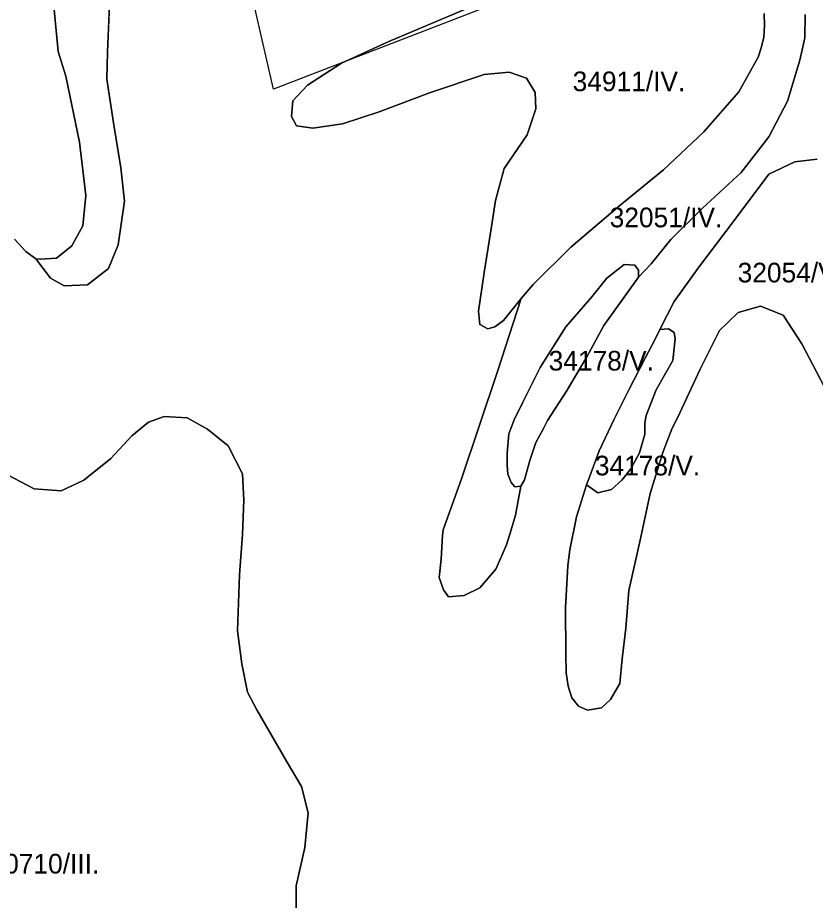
# Model space of a CAD drawing. Extents: x -521621 to -516761, y -1190184 to -1184927.
# Drawn here: x -520715 to -520107, y -1188092 to -1187419 of the extents above; entities that cross this region are included whole.
import ezdxf

# ---------------------------------------------------------------- set-up
doc = ezdxf.new("R2010")
doc.units = 0
doc.layers.add('BPEJ_s', color=7, linetype='Continuous')
doc.layers.add('odvodneni_s', color=7, linetype='Continuous')

msp = doc.modelspace()

# ---------------------------------------------------------------- linework, layer by layer
at = {"layer": 'BPEJ_s'}
for p, q in [((-520646.81, -1187445.43), (-520644.86, -1187402.32)), ((-520358.86, -1187406.5), (-520432.14, -1187437.52)), ((-520115.05, -1187434.6), (-520114.84, -1187416.89)), ((-520432.14, -1187437.52), (-520468.22, -1187453.88)), ((-520117.15, -1187443.67), (-520115.05, -1187434.6)), ((-520647.21, -1187466.2), (-520646.81, -1187445.43)), ((-520118.83, -1187451.64), (-520117.15, -1187443.67)), ((-520468.22, -1187453.88), (-520494.15, -1187470.8)), ((-520128.33, -1187482.99), (-520118.83, -1187451.64)), ((-520642.11, -1187499.52), (-520647.21, -1187466.2)), ((-520401.13, -1187476.44), (-520359.55, -1187462.56)), ((-520359.55, -1187462.56), (-520340.56, -1187460.66)), ((-520340.56, -1187460.66), (-520327.27, -1187465.42)), ((-520327.27, -1187465.42), (-520320.62, -1187476.34)), ((-520494.15, -1187470.8), (-520505.42, -1187482.65)), ((-520439.47, -1187491.11), (-520401.13, -1187476.44)), ((-520320.62, -1187476.34), (-520320.15, -1187488.69)), ((-520505.42, -1187482.65), (-520506.55, -1187494.49)), ((-520142.57, -1187510.07), (-520128.33, -1187482.99)), ((-520467.65, -1187500.13), (-520439.47, -1187491.11)), ((-520320.15, -1187488.69), (-520326.79, -1187508.65)), ((-520636.63, -1187533.62), (-520642.11, -1187499.52)), ((-520506.55, -1187494.49), (-520502.6, -1187501.82)), ((-520490.2, -1187503.52), (-520467.65, -1187500.13)), ((-520502.6, -1187501.82), (-520490.2, -1187503.52)), ((-520326.79, -1187508.65), (-520344.36, -1187534.3)), ((-520163.46, -1187537.15), (-520142.57, -1187510.07)), ((-520105.54, -1187527.18), (-520122.63, -1187529.08)), ((-520633.89, -1187559.09), (-520636.63, -1187533.62)), ((-520344.36, -1187534.3), (-520351.01, -1187558.53)), ((-520122.63, -1187529.08), (-520142.57, -1187538.58)), ((-520193.37, -1187564.71), (-520163.46, -1187537.15)), ((-520142.57, -1187538.58), (-520168.21, -1187572.79)), ((-520638.59, -1187592.41), (-520633.89, -1187559.09)), ((-520351.01, -1187558.53), (-520354.33, -1187581.81)), ((-520217.11, -1187588.46), (-520193.37, -1187564.71)), ((-520168.21, -1187572.79), (-520195.75, -1187609.37)), ((-520717.71, -1187588.1), (-520709.09, -1187597.5)), ((-520354.33, -1187581.81), (-520359.55, -1187613.64)), ((-520232.31, -1187606.99), (-520217.11, -1187588.46)), ((-520646.03, -1187610.44), (-520638.59, -1187592.41)), ((-520709.09, -1187597.5), (-520701.26, -1187602.99)), ((-520701.26, -1187602.99), (-520690.29, -1187617.89)), ((-520241.8, -1187616.97), (-520232.31, -1187606.99)), ((-520662.09, -1187622.98), (-520646.03, -1187610.44)), ((-520359.55, -1187613.64), (-520363.83, -1187643.1)), ((-520195.75, -1187609.37), (-520214.74, -1187635.5)), ((-520690.29, -1187617.89), (-520679.72, -1187623.76)), ((-520268.39, -1187654.03), (-520241.8, -1187616.97)), ((-520679.72, -1187623.76), (-520662.09, -1187622.98)), ((-520331.39, -1187633.36), (-520349.25, -1187689.02)), ((-520344.84, -1187650.23), (-520331.39, -1187633.36)), ((-520214.74, -1187635.5), (-520225.66, -1187656.88)), ((-520165.84, -1187644.05), (-520148.74, -1187639.3)), ((-520148.74, -1187639.3), (-520131.65, -1187645.95)), ((-520363.83, -1187643.1), (-520362.88, -1187653.08)), ((-520180.08, -1187657.83), (-520165.84, -1187644.05)), ((-520131.65, -1187645.95), (-520117.41, -1187667.8)), ((-520362.88, -1187653.08), (-520356.71, -1187656.4)), ((-520356.71, -1187656.4), (-520351.48, -1187654.98)), ((-520351.48, -1187654.98), (-520344.84, -1187650.23)), ((-520281.21, -1187677.78), (-520268.39, -1187654.03)), ((-520225.66, -1187656.88), (-520229.46, -1187664.95)), ((-520194.8, -1187687.28), (-520180.08, -1187657.83)), ((-520229.46, -1187664.95), (-520236.58, -1187678.26)), ((-520117.41, -1187667.8), (-520097.46, -1187705.81)), ((-520296.88, -1187703.91), (-520281.21, -1187677.78)), ((-520236.58, -1187678.26), (-520249.4, -1187703.44)), ((-520349.25, -1187689.02), (-520376.91, -1187770.9)), ((-520211.89, -1187723.86), (-520194.8, -1187687.28)), ((-520311.12, -1187726.24), (-520296.88, -1187703.91)), ((-520249.4, -1187703.44), (-520260.32, -1187725.29)), ((-520615.47, -1187727.67), (-520628.29, -1187738.12)), ((-520603.6, -1187723.39), (-520615.47, -1187727.67)), ((-520586.04, -1187724.34), (-520603.6, -1187723.39)), ((-520570.37, -1187732.89), (-520586.04, -1187724.34)), ((-520314.58, -1187733.08), (-520311.12, -1187726.24)), ((-520260.32, -1187725.29), (-520271.81, -1187749.37)), ((-520216.24, -1187732.15), (-520211.89, -1187723.86)), ((-520554.7, -1187745.72), (-520570.37, -1187732.89)), ((-520320.16, -1187743.09), (-520314.58, -1187733.08)), ((-520222.98, -1187750.07), (-520216.24, -1187732.15)), ((-520628.29, -1187738.12), (-520644.18, -1187755.37)), ((-520324.81, -1187756.81), (-520320.16, -1187743.09)), ((-520543.78, -1187767.1), (-520554.7, -1187745.72)), ((-520271.81, -1187749.37), (-520279.71, -1187770.77)), ((-520644.18, -1187755.37), (-520664.73, -1187771.82)), ((-520232.98, -1187781.94), (-520222.98, -1187750.07)), ((-520328.77, -1187771.7), (-520324.81, -1187756.81)), ((-520702.53, -1187778.4), (-520723.08, -1187767.71)), ((-520542.83, -1187787.05), (-520543.78, -1187767.1)), ((-520664.73, -1187771.82), (-520681.99, -1187780.04)), ((-520376.91, -1187770.9), (-520390.76, -1187809.62)), ((-520335.74, -1187798.45), (-520331.56, -1187776.35)), ((-520331.56, -1187776.35), (-520328.77, -1187771.7)), ((-520281.57, -1187775.42), (-520289.01, -1187799.85)), ((-520279.71, -1187770.77), (-520281.57, -1187775.42)), ((-520681.99, -1187780.04), (-520702.53, -1187778.4)), ((-520240.65, -1187817.53), (-520232.98, -1187781.94)), ((-520543.78, -1187813.18), (-520542.83, -1187787.05)), ((-520339, -1187809.62), (-520335.74, -1187798.45)), ((-520289.01, -1187799.85), (-520294.12, -1187824.97)), ((-520390.76, -1187809.62), (-520391.36, -1187814.13)), ((-520342.46, -1187821.26), (-520339, -1187809.62)), ((-520546.15, -1187844.06), (-520543.78, -1187813.18)), ((-520391.36, -1187814.13), (-520392.31, -1187832.18)), ((-520350.53, -1187839.79), (-520342.46, -1187821.26)), ((-520249.26, -1187855.91), (-520240.65, -1187817.53)), ((-520294.12, -1187824.97), (-520295.75, -1187836.84)), ((-520392.31, -1187832.18), (-520393.74, -1187845.96)), ((-520295.75, -1187836.84), (-520297.61, -1187869.17)), ((-520547.58, -1187886.82), (-520546.15, -1187844.06)), ((-520362.88, -1187854.04), (-520350.53, -1187839.79)), ((-520393.74, -1187845.96), (-520390.42, -1187855.46)), ((-520390.42, -1187855.46), (-520386.62, -1187860.69)), ((-520374.75, -1187859.74), (-520362.88, -1187854.04)), ((-520251.58, -1187884.76), (-520249.26, -1187855.91)), ((-520386.62, -1187860.69), (-520374.75, -1187859.74)), ((-520297.61, -1187869.17), (-520297.38, -1187904.07)), ((-520544.25, -1187912), (-520547.58, -1187886.82)), ((-520254.37, -1187908.02), (-520251.58, -1187884.76)), ((-520297.38, -1187904.07), (-520296.92, -1187918.72)), ((-520256, -1187926.86), (-520254.37, -1187908.02)), ((-520539.98, -1187933.38), (-520544.25, -1187912)), ((-520296.92, -1187918.72), (-520295.52, -1187928.96)), ((-520295.52, -1187928.96), (-520292.73, -1187937.8)), ((-520263.2, -1187938.96), (-520256, -1187926.86)), ((-520532.75, -1187947.05), (-520539.98, -1187933.38)), ((-520292.73, -1187937.8), (-520287.62, -1187944.08)), ((-520287.62, -1187944.08), (-520280.64, -1187947.1)), ((-520269.95, -1187945.48), (-520263.2, -1187938.96)), ((-520510.2, -1187986.21), (-520532.75, -1187947.05)), ((-520280.64, -1187947.1), (-520269.95, -1187945.48)), ((-520498.93, -1188005.46), (-520510.2, -1187986.21)), ((-520493.62, -1188025.37), (-520498.93, -1188005.46)), ((-520496.27, -1188051.92), (-520493.62, -1188025.37)), ((-520502.91, -1188081.12), (-520496.27, -1188051.92)), ((-520502.91, -1188129.57), (-520502.91, -1188081.12))]:
    msp.add_line(p, q, dxfattribs=at)
for points in [[(-520691.47, -1187370.18), (-520684.42, -1187445.04), (-520678.54, -1187463.85), (-520667.97, -1187514.02), (-520663.27, -1187554.78), (-520665.62, -1187577.91), (-520673.84, -1187593.19), (-520685.59, -1187602.6), (-520698.13, -1187603.38), (-520701.26, -1187602.99), (-520709.09, -1187597.5), (-520717.71, -1187588.1)], [(-520644.86, -1187402.32), (-520646.81, -1187445.43), (-520647.21, -1187466.2), (-520642.11, -1187499.52), (-520636.63, -1187533.62), (-520633.89, -1187559.09), (-520638.59, -1187592.41), (-520646.03, -1187610.44), (-520662.09, -1187622.98), (-520679.72, -1187623.76), (-520690.29, -1187617.89), (-520701.26, -1187602.99), (-520698.13, -1187603.38), (-520685.59, -1187602.6), (-520673.84, -1187593.19), (-520665.62, -1187577.91), (-520663.27, -1187554.78), (-520667.97, -1187514.02), (-520678.54, -1187463.85), (-520684.42, -1187445.04), (-520691.47, -1187370.18)], [(-520146.02, -1187416.05), (-520145.81, -1187425.12), (-520146.23, -1187433.97), (-520148.13, -1187441.35), (-520150.64, -1187449.26), (-520165.36, -1187475.87), (-520191.95, -1187506.27), (-520222.81, -1187535.25), (-520256.05, -1187562.33), (-520293.56, -1187594.17), (-520322.05, -1187622.67), (-520331.39, -1187633.36), (-520344.84, -1187650.23), (-520351.48, -1187654.98), (-520356.71, -1187656.4), (-520362.88, -1187653.08), (-520363.83, -1187643.1), (-520359.55, -1187613.64), (-520354.33, -1187581.81), (-520351.01, -1187558.53), (-520344.36, -1187534.3), (-520326.79, -1187508.65), (-520320.15, -1187488.69), (-520320.62, -1187476.34), (-520327.27, -1187465.42), (-520340.56, -1187460.66), (-520359.55, -1187462.56), (-520401.13, -1187476.44), (-520439.47, -1187491.11), (-520467.65, -1187500.13), (-520490.2, -1187503.52), (-520502.6, -1187501.82), (-520506.55, -1187494.49), (-520505.42, -1187482.65), (-520494.15, -1187470.8), (-520468.22, -1187453.88), (-520432.14, -1187437.52), (-520358.86, -1187406.5)], [(-520114.84, -1187416.89), (-520115.05, -1187434.6), (-520117.15, -1187443.67), (-520118.83, -1187451.64), (-520128.33, -1187482.99), (-520142.57, -1187510.07), (-520163.46, -1187537.15), (-520193.37, -1187564.71), (-520217.11, -1187588.46), (-520232.31, -1187606.99), (-520241.8, -1187616.97), (-520241.8, -1187611.74), (-520244.65, -1187607.94), (-520252.72, -1187607.47), (-520266.02, -1187617.92), (-520277.41, -1187632.17), (-520297.36, -1187654.98), (-520316.82, -1187685.86), (-520330.12, -1187712.46), (-520336.76, -1187725.77), (-520340.62, -1187736.57), (-520342.02, -1187751.23), (-520342.02, -1187760.53), (-520341.55, -1187767.28), (-520339, -1187773.56), (-520336.21, -1187777.05), (-520331.56, -1187776.35), (-520335.74, -1187798.45), (-520339, -1187809.62), (-520342.46, -1187821.26), (-520350.53, -1187839.79), (-520362.88, -1187854.04), (-520374.75, -1187859.74), (-520386.62, -1187860.69), (-520390.42, -1187855.46), (-520393.74, -1187845.96), (-520392.31, -1187832.18), (-520391.36, -1187814.13), (-520390.76, -1187809.62), (-520376.91, -1187770.9), (-520349.25, -1187689.02), (-520331.39, -1187633.36), (-520322.05, -1187622.67), (-520293.56, -1187594.17), (-520256.05, -1187562.33), (-520222.81, -1187535.25), (-520191.95, -1187506.27), (-520165.36, -1187475.87), (-520150.64, -1187449.26), (-520148.13, -1187441.35), (-520146.23, -1187433.97), (-520145.81, -1187425.12), (-520146.02, -1187416.05)], [(-520097.46, -1187705.81), (-520117.41, -1187667.8), (-520131.65, -1187645.95), (-520148.74, -1187639.3), (-520165.84, -1187644.05), (-520180.08, -1187657.83), (-520194.8, -1187687.28), (-520211.89, -1187723.86), (-520216.24, -1187732.15), (-520222.98, -1187750.07), (-520232.98, -1187781.94), (-520240.65, -1187817.53), (-520249.26, -1187855.91), (-520251.58, -1187884.76), (-520254.37, -1187908.02), (-520256, -1187926.86), (-520263.2, -1187938.96), (-520269.95, -1187945.48), (-520280.64, -1187947.1), (-520287.62, -1187944.08), (-520292.73, -1187937.8), (-520295.52, -1187928.96), (-520296.92, -1187918.72), (-520297.38, -1187904.07), (-520297.61, -1187869.17), (-520295.75, -1187836.84), (-520294.12, -1187824.97), (-520289.01, -1187799.85), (-520281.57, -1187775.42), (-520272.74, -1187781.47), (-520262.51, -1187778.91), (-520254.6, -1187771.93), (-520247.63, -1187763.33), (-520241.12, -1187751), (-520236.93, -1187736.81), (-520236.93, -1187728.2), (-520236.11, -1187722.44), (-520228.51, -1187702.96), (-520215.69, -1187680.63), (-520213.79, -1187664), (-520214.74, -1187659.25), (-520219.01, -1187656.4), (-520225.66, -1187656.88), (-520214.74, -1187635.5), (-520195.75, -1187609.37), (-520168.21, -1187572.79), (-520142.57, -1187538.58), (-520122.63, -1187529.08), (-520105.54, -1187527.18)], [(-520723.08, -1187767.71), (-520702.53, -1187778.4), (-520681.99, -1187780.04), (-520664.73, -1187771.82), (-520644.18, -1187755.37), (-520628.29, -1187738.12), (-520615.47, -1187727.67), (-520603.6, -1187723.39), (-520586.04, -1187724.34), (-520570.37, -1187732.89), (-520554.7, -1187745.72), (-520543.78, -1187767.1), (-520542.83, -1187787.05), (-520543.78, -1187813.18), (-520546.15, -1187844.06), (-520547.58, -1187886.82), (-520544.25, -1187912), (-520539.98, -1187933.38), (-520532.75, -1187947.05), (-520510.2, -1187986.21), (-520498.93, -1188005.46), (-520493.62, -1188025.37), (-520496.27, -1188051.92), (-520502.91, -1188081.12), (-520502.91, -1188105.01)]]:
    msp.add_lwpolyline(points, dxfattribs=at)
for points in [[(-520331.56, -1187776.35), (-520336.21, -1187777.05), (-520339, -1187773.56), (-520341.55, -1187767.28), (-520342.02, -1187760.53), (-520342.02, -1187751.23), (-520340.62, -1187736.57), (-520336.76, -1187725.77), (-520330.12, -1187712.46), (-520316.82, -1187685.86), (-520297.36, -1187654.98), (-520277.41, -1187632.17), (-520266.02, -1187617.92), (-520252.72, -1187607.47), (-520244.65, -1187607.94), (-520241.8, -1187611.74), (-520241.8, -1187616.97), (-520268.39, -1187654.03), (-520281.21, -1187677.78), (-520296.88, -1187703.91), (-520311.12, -1187726.24), (-520314.58, -1187733.08), (-520320.16, -1187743.09), (-520324.81, -1187756.81), (-520328.77, -1187771.7)], [(-520281.57, -1187775.42), (-520279.71, -1187770.77), (-520271.81, -1187749.37), (-520260.32, -1187725.29), (-520249.4, -1187703.44), (-520236.58, -1187678.26), (-520229.46, -1187664.95), (-520225.66, -1187656.88), (-520219.01, -1187656.4), (-520214.74, -1187659.25), (-520213.79, -1187664), (-520215.69, -1187680.63), (-520228.51, -1187702.96), (-520236.11, -1187722.44), (-520236.93, -1187728.2), (-520236.93, -1187736.81), (-520241.12, -1187751), (-520247.63, -1187763.33), (-520254.6, -1187771.93), (-520262.51, -1187778.91), (-520272.74, -1187781.47)]]:
    msp.add_lwpolyline(points, close=True, dxfattribs=at)
at = {"layer": 'odvodneni_s'}
msp.add_lwpolyline([(-520593.76, -1187152.58), (-520541.54, -1187164.45), (-520515.42, -1187165.48), (-520393.78, -1187200.38), (-520326.56, -1187211.63), (-520292.57, -1187219), (-520207.51, -1187243.56), (-520108.49, -1187272.64), (-520108.69, -1187281.29), (-520123.82, -1187309.68), (-520145.11, -1187328.82), (-520175.98, -1187347.03), (-520205.14, -1187354.13), (-520224.13, -1187362.31), (-520261.94, -1187373.88), (-520520.06, -1187473.85)], close=True, dxfattribs=at)

# ---------------------------------------------------------------- texts
at = {"layer": 'BPEJ_s'}
for s, p in [('34911/IV.', (-520292.07, -1187475.28)), ('32051/IV.', (-520263.83, -1187579.04)), ('32054/V.', (-520166.24, -1187621.08)), ('34178/V.', (-520310.37, -1187688.26)), ('34178/V.', (-520275.09, -1187768.21)), ('30710/III.', (-520736.67, -1188071.75))]:
    msp.add_text(s, height=15, dxfattribs=at).set_placement(p)

doc.saveas('drawing.dxf')
